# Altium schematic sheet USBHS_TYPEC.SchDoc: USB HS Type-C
size A4; Date: Not used; ApprovedBy: Not used; CheckedBy: Not used; Author: Not used; CompanyName: STMicroelectronics; DrawnBy: Not used; Engineer: Not used; Organization: Not used; Address1: Not used; Address2: Not used; Address3: Not used; Address4: Not used; DocumentNumber: Not used; Revision: Not used; SheetNumber: 9; SheetTotal: 16
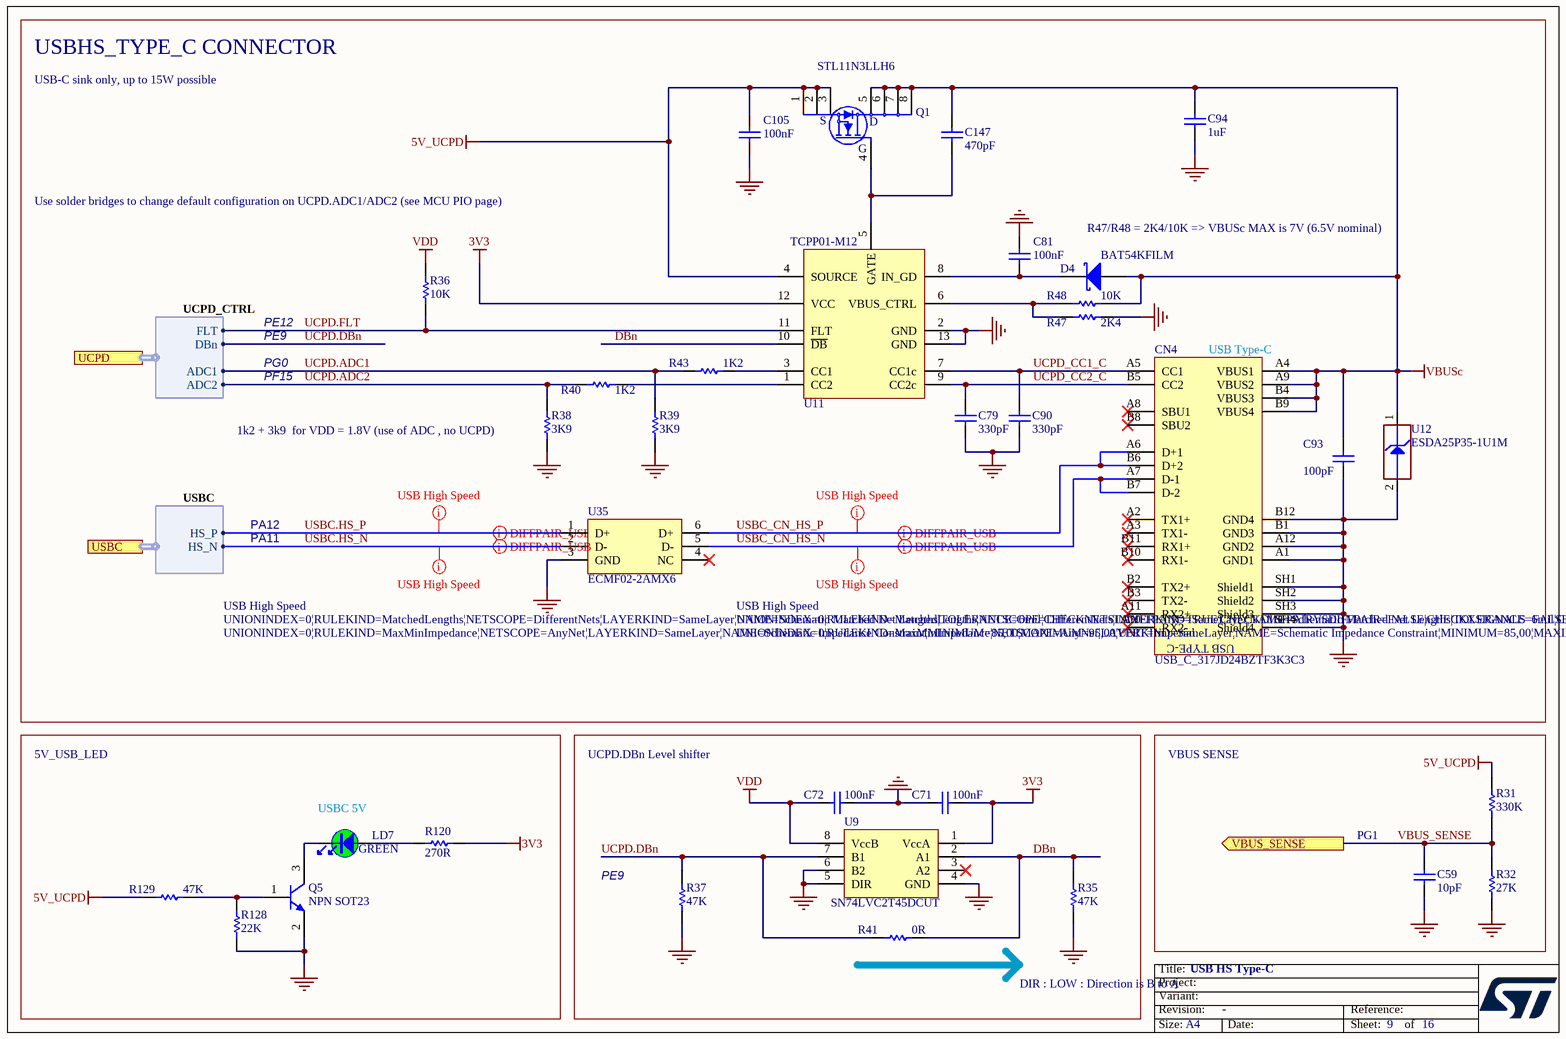
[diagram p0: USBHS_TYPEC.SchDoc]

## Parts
C59  value 10pF  [C0603]  (hidden comment: Capacitor)
C71  value 100nF  [C0402]  (hidden comment: Capacitor)
C72  value 100nF  [C0402]  (hidden comment: Capacitor)
C79  value 330pF  [C0402]  (hidden comment: Capacitor)
C81  value 100nF  [C0603]  (hidden comment: Capacitor)
C90  value 330pF  [C0402]  (hidden comment: Capacitor)
C93  value 100pF  [C0402]  (hidden comment: Capacitor)
C94  value 1uF  [C0402]  (hidden comment: Capacitor)
C105  value 100nF  [C0603]  (hidden comment: Capacitor)
C147  value 470pF  [C0402]  (hidden comment: Capacitor)
CN4  value USB_C_317JD24BZTF3K3C3  [CON_USB-TYPEC_COXOC_317JD24BZTF3K3C3]  (hidden comment: USB_TYPE_C_Receptacle_317JD24BZTF3K3C3)
D4  value BAT54KFILM  [DIO_SOD523_1A_2K]  (hidden comment: SCHOTTKY_1A_2K)
LD7  value GREEN  [LED_0603_OSRAM_LG-Q396-PS-35_GREEN_1A2K_H0P4]  (hidden comment: LED_green)
Q1  STL11N3LLH6  [MOS_POWERFLAT_3P3X3P3_P065]
Q5  value NPN SOT23  [NPN_SOT23]  (hidden comment: 9013-SOT23)
R31  value 330K  [R0603]  (hidden comment: Resistor)
R32  value 27K  [R0603]  (hidden comment: Resistor)
R35  value 47K  [R0603]  (hidden comment: Resistor)
R36  value 10K  [R0603]  (hidden comment: Resistor)
R37  value 47K  [R0603]  (hidden comment: Resistor)
R38  value 3K9  [R0402]  (hidden comment: Resistor)
R39  value 3K9  [R0402]  (hidden comment: Resistor)
R40  value 1K2  [R0402]  (hidden comment: Resistor)
R41  value 0R  [R0402]  (hidden comment: Resistor)
R43  value 1K2  [R0402]  (hidden comment: Resistor)
R47  value 2K4  [R0402]  (hidden comment: Resistor)
R48  value 10K  [R0402]  (hidden comment: Resistor)
R120  value 270R  [R0402]  (hidden comment: Resistor)
R128  value 22K  [R0603]  (hidden comment: Resistor)
R129  value 47K  [R0603]  (hidden comment: Resistor)
U9  SN74LVC2T45DCUT  [ICC_VSSOP8_DCU_R-PDSO-G8_2X2P30_P050]
U11  TCPP01-M12  [ICC_QFN12L-EPAD_3X3_P050]
U12  value ESDA25P35-1U1M  [ESD_QFN1610_2N_1K_2A]  (hidden comment: ESD-TRANSIL)
U35  ECMF02-2AMX6  [ESD_QFN-6L_1P7X1P5_P050]

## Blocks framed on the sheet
USBHS_TYPE_C CONNECTOR: C79 C81 C90 C93 C94 C105 C147 CN4 D4 Q1 R36 R38-R40 R43 R47 R48 U11 U12 U35

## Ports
UCPD (harness UCPD_CTRL), USBC (harness USBC), VBUS_SENSE (out)

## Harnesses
USBC: HS_P, HS_N
UCPD_CTRL: FLT, DBn, ADC1, ADC2

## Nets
3V3: C71.2 R120.2 U9.1(VccA) U11.12(VCC)
5V_UCPD: C105.1 Q1.1(S) Q1.2(S) Q1.3(S) R31.2 R129.1 U11.4(SOURCE)
GND: C59.1 C71.1 C72.2 C79.1 C81.1 C90.1 C93.1 C94.1 C105.2 CN4.A1(GND1) CN4.A12(GND2) CN4.B1(GND3) CN4.B12(GND4) CN4.SH1(Shield1) CN4.SH2(Shield2) CN4.SH3(Shield3) CN4.SH4(Shield4) Q5.2(E) R32.1 R35.1 R37.2 R38.1 R39.1 R47.2 R128.1 U9.4(GND) U9.5(DIR) U9.6(B2) U11.2(GND) U11.13(GND) U12.2(GND) U35.3(GND)
VBUSc: C93.2 C94.2 C147.2 CN4.A4(VBUS1) CN4.A9(VBUS2) CN4.B4(VBUS3) CN4.B9(VBUS4) D4.1(A) Q1.5(D) Q1.6(D) Q1.7(D) Q1.8(D) R48.2 U12.1(IO1)
VDD: C72.1 R36.2 U9.8(VccB)
DBn: R35.2 R41.2 U9.2(A1) U11.10(~{DB})
UCPD.ADC1: R39.2 R43.1 ; port UCPD.ADC1
UCPD.ADC2: R38.2 R40.1 ; port UCPD.ADC2
UCPD.DBn: R37.1 R41.1 U9.7(B1) ; port UCPD.DBn
UCPD.FLT: R36.1 U11.11(FLT) ; port UCPD.FLT
UCPD_CC1_C: C90.2 CN4.A5(CC1) U11.7(CC1c)
UCPD_CC2_C: C79.2 CN4.B5(CC2) U11.9(CC2c)
USBC.HS_N: U35.2(D-) ; port USBC.HS_N
USBC.HS_P: U35.1(D+) ; port USBC.HS_P
USBC_CN_HS_N: CN4.A7(D-1) CN4.B7(D-2) U35.5(D-)
USBC_CN_HS_P: CN4.A6(D+1) CN4.B6(D+2) U35.6(D+)
VBUS_SENSE: C59.2 R31.1 R32.2 ; port VBUS_SENSE
NetC81_2: C81.2 D4.2(K) U11.8(IN_GD)
NetC147_1: C147.1 Q1.4(G) U11.5(GATE)
NetLD7_1: LD7.1 R120.1
NetLD7_2: LD7.2 Q5.3(C)
NetQ5_1: Q5.1(B) R128.2 R129.2
NetR40_2: R40.2 U11.1(CC2)
NetR43_2: R43.2 U11.3(CC1)
NetR47_1: R47.1 R48.1 U11.6(VBUS_CTRL)

Not connected (* = marked no-connect by the designer): CN4 A2(TX1+)* A3(TX1-)* A8(SBU1)* A10(RX2-)* A11(RX2+)* B2(TX2+)* B3(TX2-)* B8(SBU2)* B10(RX1-)* B11(RX1+)*; U9 3(A2)*; U35 4(NC)*

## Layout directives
differential pair; rule Impedance Constraint [Min = 85.00    Max = 95.00    ]: USBC.HS_N, USBC.HS_P, USBC_CN_HS_N, USBC_CN_HS_P
rule Matched Net Lengths [Tolerance = 6mil]; rule Routing Layers [TopLayer - Enabled BottomLayer - Disabled]; rule Impedance Constraint [Min = 85.00    Max = 95.00    ]; net class USB High Speed: USBC.HS_P, USBC_CN_HS_P
rule Matched Net Lengths [Tolerance = 0mil]; rule Routing Layers [TopLayer - Enabled BottomLayer - Disabled]; rule Impedance Constraint [Min = 85.00    Max = 95.00    ]; net class USB High Speed: USBC.HS_N, USBC_CN_HS_N

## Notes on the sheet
- USB-C sink only, up to 15W possible
- Use solder bridges to change default configuration on UCPD.ADC1/ADC2 (see MCU PIO page)
- (near D4) R47/R48 = 2K4/10K => VBUSc MAX is 7V (6.5V nominal)
- PG0
- PF15
- PE12
- PE9
- (near CN4) USB Type-C
- (near R38) 1k2 + 3k9  for VDD = 1.8V (use of ADC , no UCPD)
- PA12
- PA11
- 5V_USB_LED
- UCPD.DBn Level shifter
- VBUS SENSE
- (near LD7) USBC 5V
- PG1
- (near R41) DIR : LOW : Direction is B to A

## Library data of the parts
C59 = MCD-00637: Capacitor, MLCC, 10pF, 50V, NPO, +/-5%, 0603, T=0.8mm; Manufacturer_Part_Number: CC0603JRNPO9BN100; Manufacturer: YAGEO; Part_Preference: Recommended; Order_Code_RS: 616-9054; Component_Country_Of_Origin: China
C71 C72 = MCD-00006: Capacitor, MLCC, 100nF, 16V, X7R, +/-10%, 0402, T=0.5mm; Manufacturer_Part_Number: CC0402KRX7R7BB104; Manufacturer: YAGEO; Part_Preference: Recommended; Order_Code_RS: 616-9701; Component_Country_Of_Origin: China
C79 C90 = MCD-01579: Capacitor, MLCC, 330pF, 50V, NPO, +/-5%, 0402, T=0.5mm; Manufacturer: YAGEO; Manufacturer_Part_Number: CC0402JRNPO9BN331; Part_Preference: Recommended; Component_Country_Of_Origin: China
C81 C105 = MCD-01099: Capacitor, MLCC, 100nF, 50V, X7R, +/-10%, 0603, T=0.8mm; Manufacturer_Part_Number: CC0603KRX7R9BB104; Manufacturer: YAGEO; BMS_Part_Number: 9142278; Part_Preference: Recommended; Order_Code_RS: 669-8767; Component_Country_Of_Origin: China
C93 = MCD-00205: Capacitor, MLCC, 100pF, 50V, NPO, +/-5%, 0402, T=0.5mm; Part_Preference: Recommended; Manufacturer: YAGEO; Manufacturer_Part_Number: CC0402JRNPO9BN101; Component_Country_Of_Origin: China
C94 = MCD-02609: Capacitor, MLCC, 1uF, 25V, X5R, +/-10%, 0402, T=0.5mm; Part_Preference: Recommended; Manufacturer: YAGEO; Manufacturer_Part_Number: CC0402KRX5R8BB105
C147 = MCD-00724: Capacitor, MLCC, 470pF, 50V, NPO, +/-5%, 0402, T=0.5mm; Part_Preference: Recommended; Manufacturer: YAGEO; Manufacturer_Part_Number: CC0402JRNPO9BN471; Order_Code_RS: 199-2186; Component_Country_Of_Origin: China
CN4 = MCD-01108: USB_TypeC, SMD+DIP, T= 2.96mm (for 1.6mm pcb); Part_Type: Connector; Manufacturer: CHANT SINCERE (COXOC); Part_Preference: Recommended; Component_Country_Of_Origin: Unknown
D4 = MCD-01677: Small signal Schottky diodes; Part_Type: Diode; Manufacturer: STMICROELECTRONICS; BMS_Part_Number: 9151123; Part_Preference: Recommended; Manufacturer_HQ_COO: EU; Component_Country_Of_Origin: China
LD7 = MCD-00588: LED Green, 0603 SMD, Forward Voltage Typ=2V, Max=2.5V; Part_Type: Display; Manufacturer_Part_Number: LG Q396-PS-35; Manufacturer: OSRAM OPTO SEMICONDUCTORS; Part_Preference: Recommended; Alternate_Internal_Part_Number: MCD-02400; Component_Country_Of_Origin: Unknown; ShowFields: YES; ID: 3155
Q1 = MCD-01810: N-channel 30 V, 6 mΩ typ, 11 A STripFET™ H6, Power MOSFET in a PowerFLAT™ 3.3x3.3 package; BMS_Part_Number: 9153561; Part_Type: IC; Part_Preference: Recommended; Manufacturer: STMICROELECTRONICS; Manufacturer_HQ_COO: EU; Component_Country_Of_Origin: China
Q5 = MCD-00073: NPN Bipolar Transistor; Part_Type: IC; Manufacturer_Part_Number: BSR14; Manufacturer: ON SEMICONDUCTOR; Part_Preference: Recommended; Component_Country_Of_Origin: Unknown
R31 = MCD-00458: Resistor, 330K, 0603, +/-1%, 1/10W; Manufacturer_Part_Number: RC0603FR-07330KL; Manufacturer: YAGEO; Part_Preference: Recommended; Component_Country_Of_Origin: China
R32 = MCD-00444: Resistor, 27K, 0603, +/-1%, 1/10W; Manufacturer_Part_Number: RC0603FR-0727KL; Manufacturer: YAGEO; Part_Preference: Recommended; Component_Country_Of_Origin: China
R35 = MCD-00222: Resistor, 47K, 0603, 1%, 1/10W; Part_Preference: Recommended; Manufacturer: YAGEO; Manufacturer_Part_Number: RC0603FR-0747KL; Component_Country_Of_Origin: China
R36 = MCD-00220: Resistor, 10K, 0603, +/-1%, 1/10W; Manufacturer_Part_Number: RC0603FR-0710KL; Manufacturer: YAGEO; Part_Preference: Recommended; Component_Country_Of_Origin: China
R37 R129 = MCD-00222: Resistor, 47K, 0603, 1%, 1/10W; Manufacturer_Part_Number: RC0603FR-0747KL; Manufacturer: YAGEO; Part_Preference: Recommended; Component_Country_Of_Origin: China
R38 R39 = MCD-02455: Resistor, 3K9, 0402, +/-1%, 1/16W, +/-100ppm/°C; Part_Preference: Recommended; Manufacturer: YAGEO; Manufacturer_Part_Number: RC0402FR-073K9L; Order_Code_RS: 198-7783; Component_Country_Of_Origin: China
R40 R43 = MCD-00373: Resistor, 1K2, 0402, +/-1%, 1/16W; Part_Preference: Recommended; Manufacturer: YAGEO; Manufacturer_Part_Number: RC0402FR-071K2L; Component_Country_Of_Origin: China
R41 = MCD-00052: Resistor, 0R, 0402, +/-5%, 1/16W; Manufacturer_Part_Number: RC0402JR-070RL; Manufacturer: YAGEO; Part_Preference: Recommended; Order_Code_RS: 618-5804; Component_Country_Of_Origin: China
R47 = MCD-00433: Resistor, 2K4, 0402, +/-1%, 1/16W; Part_Preference: Recommended; Manufacturer: YAGEO; Manufacturer_Part_Number: RC0402FR-072K4L; Component_Country_Of_Origin: China
R48 = MCD-00053: Resistor, 10K, 0402, +/-1%, 1/16W; BMS_Part_Number: 9131590; Part_Preference: Recommended; Manufacturer: YAGEO; Manufacturer_Part_Number: RC0402FR-0710KL; Component_Country_Of_Origin: China
R120 = MCD-00441: Resistor, 270R, 0402, +/-1%, 1/16W; Manufacturer: YAGEO; Manufacturer_Part_Number: RC0402FR-07270RL; Part_Preference: Recommended; Component_Country_Of_Origin: China; ShowFields: YES; ID: 2838
R128 = MCD-00430: Resistor, 22K, 0603, +/-1%, 1/10W; Manufacturer_Part_Number: RC0603FR-0722KL; Manufacturer: YAGEO; Part_Preference: Recommended; Component_Country_Of_Origin: China
U9 = MCD-00264: Dual bit dual supply bus transceiver; Part_Type: IC; Manufacturer: TEXAS INSTRUMENTS; BMS_Part_Number: 9169311; Part_Preference: Recommended; Component_Country_Of_Origin: Thailand
U11 = MCD-01809: USB Type-C Port Protection for USB Power Delivery, PPS compliant; Part_Type: IC; Manufacturer: STMICROELECTRONICS; BMS_Part_Number: 9151145; Part_Preference: Recommended; Manufacturer_HQ_COO: EU; Component_Country_Of_Origin: Malaysia
U12 = MCD-01207: High power Transient voltage suppressor:25V/35A EOS and ESD transients protection.; Part_Type: Diode; Manufacturer: STMICROELECTRONICS; BMS_Part_Number: 9179045; Part_Preference: Recommended; Manufacturer_HQ_COO: EU; Component_Country_Of_Origin: China
U35 = MCD-00649: Common mode filter with ESD protection for USB 2.0 interface; Part_Type: Diode; Manufacturer: STMICROELECTRONICS; BMS_Part_Number: 9151138; Part_Preference: Recommended; Manufacturer_HQ_COO: EU; Component_Country_Of_Origin: China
